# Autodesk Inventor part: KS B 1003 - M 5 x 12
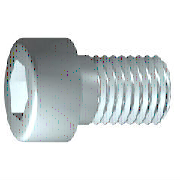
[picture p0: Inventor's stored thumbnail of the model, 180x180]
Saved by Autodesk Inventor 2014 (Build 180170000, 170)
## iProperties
IsCustomPart: 0
Created: 2009-02
Part Number: KS B 1003 - M 5 x 12
Material: 강, 연강
Description: 6각머리 태핑 나사
Document SubType Name: Modeling
Standard: KS B 1003
Designer: KYOUNG IL JANG
Standards Organization: KS
Language: ko-KR
Size Designation: M 5 x 12
Categories: <MemberInstance><Categories><Category DisplayName="조임쇠" InternalName="e4da775c-781d-43d5-af7c-5136215cf5a6" Mnemonic="FSTN"><Category DisplayName="볼트" InternalN
Density: 7.86 g/cm^3
Mass: 3.72825 g
Surface Area: 4.62573 cm^2
Volume: 0.474332 cm^3
Appearance: 강철
Author: KYOUNG IL JANG
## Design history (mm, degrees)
sketch "스케치1"
  geometry: L1 (-1.167, 0)-(12, 0); L2 (12, 0)-(12, 2.5); L3 (12, 2.5)-(2, 2.5); L4 (2, 2.5)-(1.509, 2.5); L5 (1.509, 2.5)-(0, 2.5); L6 (0, 2.5)-(0, 4.25); L7 (0, 4.25)-(-5, 4.25); L8 (-5, 4.25)-(-5, 2.309); L9 (-5, 2.309)-(-2.5, 2.309); L10 (-2.5, 2.309)-(-1.167, 0); L11 (-8.4, 0)-(15.4, 0) reference; L12 (0, -0.85)-(0, 5.1) reference; L13 (2, 2.5)-(0, 2.5)
  constraints: 22 end point, 6 parallel, 2 collinear, 2 perpendicular, 1 horizontal, 1 point on line
  dimensions: "d1" = 10 distance from line of L3.end L2 (= GEL); "d2" = 0.49086 distance of L4.end L3.end (computed from GAL); "d3" = 5 distance between parallel lines of L8 L6 (= KOH); "d4" = 2.5 distance of L8.end L9.end (= INTI); "d5" = 60 deg angle of L10 L1; "d6" = 5 diameter of L3 L1 (= GD); "d7" = 5 diameter of L5 L1 (= BDM); "d8" = 4.6188 diameter of L9 L1 (= 1.1547 x SW); "d9" = 8.5 diameter of L7 L1 (= KOD); "d26" = 12 distance between parallel lines of L12 L2 (= NLG)
revolve "본체" sketch "스케치1" stored, may be unused: angle "d10" = 90 deg
sketch "스케치2"
  geometry: L1 (0, -5.95)-(0, 5.95) reference; L2 (-5.95, 0)-(5.95, 0) reference; L3 (2.309, 0)-(1.155, -2); L4 (1.155, -2)-(-1.155, -2); L5 (-1.155, -2)-(-2.309, 0); L6 (-2.309, 0)-(-1.155, 2); L7 (-1.155, 2)-(1.155, 2); L8 (1.155, 2)-(2.309, 0); 2 further points
  constraints: 12 end point, 1 coincident, 1 horizontal alignment, 1 point on line, 12 other
extrude "슬롯" join sketch "스케치2" stored distance "d11" = 10; taper "d12" = 0 deg
workplane "Work Plane1"
fillet "Fillet2" dims "d30" = 0.1 (= R)
body "Solid1"
fillet "모깎기1" dims "d17" = 0.5 (= RR)
feature "스레드" dims "d13" = 10 (= GEL), "d14" = 0
chamfer "모따기1" distance "d15" = 0.49076 (= -0.5 x SPD + 0.5 x GD); stored, may be unused: second distance "d16" = 0.49076 (= GUL), angle "d27" = 45 deg
other parameters: "GD" = 5 (= NND) [user parameter; used in 2 equation terms], "NLG" = 12 [user parameter; used in 1 equation term], "GEL" = 10 [user parameter; used in 2 equation terms], "KOD" = 8.5 [user parameter; used in 1 equation term], "KOH" = 5 [user parameter; used in 1 equation term], "INTI" = 2.5 [user parameter; used in 1 equation term], "GAL" = 0.49076 (= 0.61345 x PTC) [user parameter; used in 1 equation term], "GUL" = 0.49076 (= 0.61345 x PTC) [user parameter; used in 1 equation term], "BDM" = 5 (= NND) [user parameter; used in 1 equation term], "SW" = 4 [user parameter; used in 2 equation terms], "RR" = 0.5 [user parameter; used in 1 equation term], "SPD" = 4.01848 (= NND - 1.2269 x PTC) [user parameter; used in 1 equation term], "d19" = 0, "d28" = 0, "d29" = 0, "R" = 0.1 [user parameter; used in 1 equation term], "PHH" = 0.2 [user parameter], "GD1" = 4.01848 (= THREADDIA - 1.2269 x PTC) [user parameter], "THREADDIA" = 5 [user parameter; used in 1 equation term], "FAWI" = 45 deg [user parameter], "TPU" = 12.5 (computed from PTC) [user parameter], "PTC" = 0.8 [user parameter; used in 5 equation terms], "NND" = 5 [user parameter; used in 3 equation terms], "TOA" = 30 deg [user parameter], "E0" = 4.62 (= 1.155 x SW) [user parameter]
